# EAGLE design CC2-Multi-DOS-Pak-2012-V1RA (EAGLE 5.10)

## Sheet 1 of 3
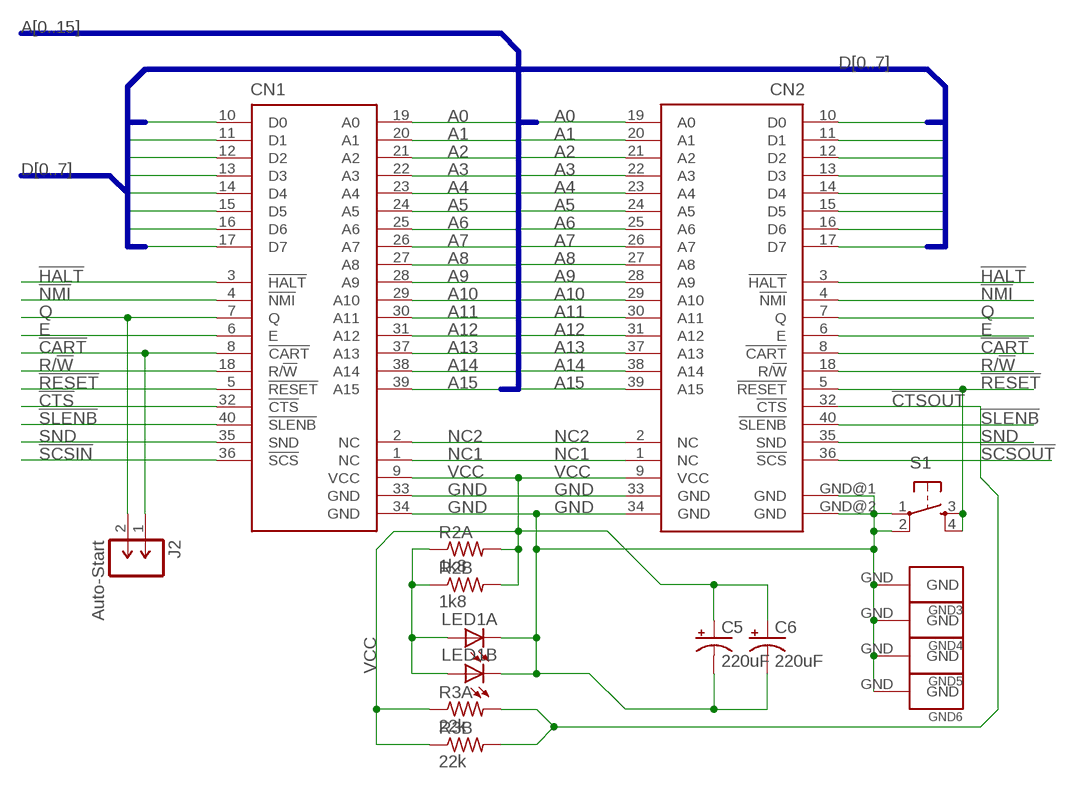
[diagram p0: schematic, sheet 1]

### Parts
C5  220uF  P-CAPACITOR-CPOL-RADIAL-1  [CPOL-RADIAL-1]
C6  220uF  P-CAPACITOR-CPOL-RADIAL-1  [CPOL-RADIAL-1]
CN1  COCO3-CARTRIDGE-PLUG-MEDIUM  [EDGE-CARD-PLUG-2X20-100-MEDIUM]
CN2  COCO3-CARTRIDGE-SLOT-HEADER/SLOT-40  [HEADER/EDGE-CARD-RECEPTACLE-2X20-100-STRAIGHT-W/EARS]
GND3  GROUNDING-STAND-OFF  [STAND-OFF]
GND4  GROUNDING-STAND-OFF  [STAND-OFF]
GND5  GROUNDING-STAND-OFF  [STAND-OFF]
GND6  GROUNDING-STAND-OFF  [STAND-OFF]
J2  Auto-Start  1X02-SIP-100-32  [SIL1X02-100]
LED1A  LED5MM  [LED5MM]
LED1B  LEDCHIPLED_1206  [CHIPLED_1206]
R2A  1k8  RESISTOR  [0207/10]
R2B  1k8  RESISTOR-M1206  [M1206]
R3A  22k  RESISTOR  [0207/10]
R3B  22k  RESISTOR-M1206  [M1206]
S1  RESET  TAC_SWITCHPTH  [TACTILE-PTH]

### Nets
!CART: CN1.8(!CART) CN2.8(!CART) J2.1
!CTS: CN1.32(!CTS) ; also sheet 3
!CTSOUT: CN2.32(!CTS) R3A.2 R3B.2
!HALT: CN1.3(!HALT) CN2.3(!HALT)
!NMI: CN1.4(!NMI) CN2.4(!NMI)
!RESET: CN1.5(!RESET) CN2.5(!RESET) S1.3 S1.4 ; also sheet 3
!SCSIN: CN1.36(!SCS) ; also sheet 2
!SCSOUT: CN2.36(!SCS) ; also sheet 2
!SLENB: CN1.40(!SLENB) CN2.40(!SLENB)
A0: CN1.19(A0) CN2.19(A0) ; also sheet 2,3
A1: CN1.20(A1) CN2.20(A1) ; also sheet 2,3
A2: CN1.21(A2) CN2.21(A2) ; also sheet 2,3
A3: CN1.22(A3) CN2.22(A3) ; also sheet 2,3
A4: CN1.23(A4) CN2.23(A4) ; also sheet 2,3
A5: CN1.24(A5) CN2.24(A5) ; also sheet 2,3
A6: CN1.25(A6) CN2.25(A6) ; also sheet 2,3
A7: CN1.26(A7) CN2.26(A7) ; also sheet 2,3
A8: CN1.27(A8) CN2.27(A8) ; also sheet 3
A9: CN1.28(A9) CN2.28(A9) ; also sheet 3
A10: CN1.29(A10) CN2.29(A10) ; also sheet 3
A11: CN1.30(A11) CN2.30(A11) ; also sheet 3
A12: CN1.31(A12) CN2.31(A12) ; also sheet 3
A13: CN1.37(A13) CN2.37(A13) ; also sheet 3
A14: CN1.38(A14) CN2.38(A14) ; also sheet 3
A15: CN1.39(A15) CN2.39(A15)
D0: CN1.10(D0) CN2.10(D0) ; also sheet 3
D1: CN1.11(D1) CN2.11(D1) ; also sheet 3
D2: CN1.12(D2) CN2.12(D2) ; also sheet 3
D3: CN1.13(D3) CN2.13(D3) ; also sheet 3
D4: CN1.14(D4) CN2.14(D4) ; also sheet 3
D5: CN1.15(D5) CN2.15(D5) ; also sheet 3
D6: CN1.16(D6) CN2.16(D6) ; also sheet 3
D7: CN1.17(D7) CN2.17(D7) ; also sheet 3
E: CN1.6(E) CN2.6(E) ; also sheet 2
GND [power]: C5.2(-) C6.2(-) CN1.33(GND) CN1.34(GND) CN2.33(GND) CN2.34(GND) CN2.GND@1(GND) CN2.GND@2(GND) GND3.GND GND4.GND GND5.GND GND6.GND LED1A.K(C) LED1B.C S1.1 S1.2 ; also sheet 2,3
N$2: LED1A.A LED1B.A R2A.1 R2B.1
NC1 [power]: CN1.1(NC) CN2.1(NC)
NC2 [power]: CN1.2(NC) CN2.2(NC)
Q: CN1.7(Q) CN2.7(Q) J2.2 ; also sheet 2
R/!W: CN1.18(R/!W) CN2.18(R/!W) ; also sheet 2
SND: CN1.35(SND) CN2.35(SND)
VCC [power]: C5.1(+) C6.1(+) CN1.9(VCC) CN2.9(VCC) R2A.2 R2B.2 R3A.1 R3B.1 ; also sheet 2,3

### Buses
A[0..15]
D[0..7]

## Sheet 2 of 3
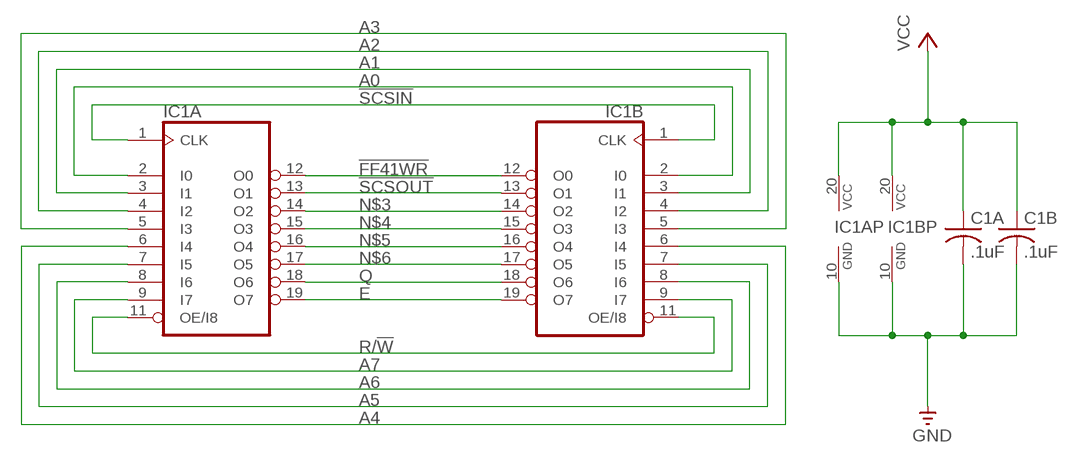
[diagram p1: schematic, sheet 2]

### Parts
C1A  .1uF  NP-CAPACITOR-C050-025X075  [C050-025X075]
C1B  .1uF  NP-CAPACITOR-C1206K  [C1206K]
IC1A  16V8  [DIL20]
IC1B  16V8-S20  [S20]

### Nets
!FF41WR: IC1A.12(O0) IC1B.12(O0) ; also sheet 3
!SCSIN: IC1A.1(CLK) IC1B.1(CLK) ; also sheet 1
!SCSOUT: IC1A.13(O1) IC1B.13(O1) ; also sheet 1
A0: IC1A.2(I0) IC1B.2(I0) ; also sheet 1,3
A1: IC1A.3(I1) IC1B.3(I1) ; also sheet 1,3
A2: IC1A.4(I2) IC1B.4(I2) ; also sheet 1,3
A3: IC1A.5(I3) IC1B.5(I3) ; also sheet 1,3
A4: IC1A.6(I4) IC1B.6(I4) ; also sheet 1,3
A5: IC1A.7(I5) IC1B.7(I5) ; also sheet 1,3
A6: IC1A.8(I6) IC1B.8(I6) ; also sheet 1,3
A7: IC1A.9(I7) IC1B.9(I7) ; also sheet 1,3
E: IC1A.19(O7) IC1B.19(O7) ; also sheet 1
GND [power]: C1A.2(-) C1B.2(-) IC1A.10(GND) IC1B.10(GND) ; also sheet 1,3
N$3: IC1A.14(O2) IC1B.14(O2)
N$4: IC1A.15(O3) IC1B.15(O3)
N$5: IC1A.16(O4) IC1B.16(O4)
N$6: IC1A.17(O5) IC1B.17(O5)
Q: IC1A.18(O6) IC1B.18(O6) ; also sheet 1
R/!W: IC1A.11(OE/I8) IC1B.11(OE/I8) ; also sheet 1
VCC [power]: C1A.1(+) C1B.1(+) IC1A.20(VCC) IC1B.20(VCC) ; also sheet 1,3

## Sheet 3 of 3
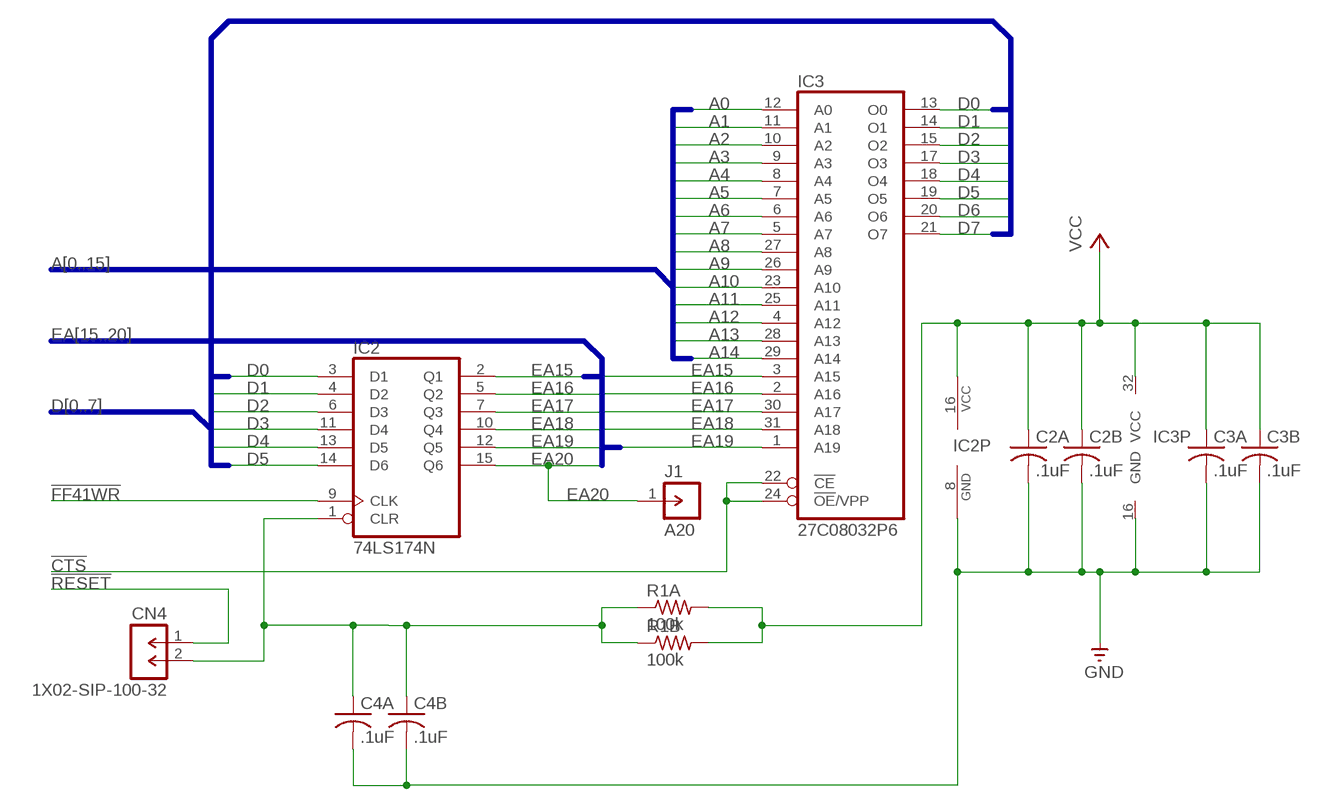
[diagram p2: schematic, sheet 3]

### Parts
C2A  .1uF  NP-CAPACITOR-C050-025X075  [C050-025X075]
C2B  .1uF  NP-CAPACITOR-C1206K  [C1206K]
C3A  .1uF  NP-CAPACITOR-C050-025X075  [C050-025X075]
C3B  .1uF  NP-CAPACITOR-C1206K  [C1206K]
C4A  .1uF  NP-CAPACITOR-C050-025X075  [C050-025X075]
C4B  .1uF  NP-CAPACITOR-C1206K  [C1206K]
CN4  1X02-SIP-100-32  [SIL1X02-100]
IC2  74LS174N  [DIL16]
IC3  27C08032P6  [DIL32-6]
J1  A20  1X01-SIL1X01-100  [SIL1X01-100]
R1A  100k  RESISTOR  [0207/10]
R1B  100k  RESISTOR-M1206  [M1206]

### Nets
!CTS: IC3.22(!CE) IC3.24(!OE!/VPP) ; also sheet 1
!FF41WR: IC2.9(CLK) ; also sheet 2
!RESET: CN4.1 ; also sheet 1
A0: IC3.12(A0) ; also sheet 1,2
A1: IC3.11(A1) ; also sheet 1,2
A2: IC3.10(A2) ; also sheet 1,2
A3: IC3.9(A3) ; also sheet 1,2
A4: IC3.8(A4) ; also sheet 1,2
A5: IC3.7(A5) ; also sheet 1,2
A6: IC3.6(A6) ; also sheet 1,2
A7: IC3.5(A7) ; also sheet 1,2
A8: IC3.27(A8) ; also sheet 1
A9: IC3.26(A9) ; also sheet 1
A10: IC3.23(A10) ; also sheet 1
A11: IC3.25(A11) ; also sheet 1
A12: IC3.4(A12) ; also sheet 1
A13: IC3.28(A13) ; also sheet 1
A14: IC3.29(A14) ; also sheet 1
D0: IC2.3(D1) IC3.13(O0) ; also sheet 1
D1: IC2.4(D2) IC3.14(O1) ; also sheet 1
D2: IC2.6(D3) IC3.15(O2) ; also sheet 1
D3: IC2.11(D4) IC3.17(O3) ; also sheet 1
D4: IC2.13(D5) IC3.18(O4) ; also sheet 1
D5: IC2.14(D6) IC3.19(O5) ; also sheet 1
D6: IC3.20(O6) ; also sheet 1
D7: IC3.21(O7) ; also sheet 1
EA15: IC2.2(Q1) IC3.3(A15)
EA16: IC2.5(Q2) IC3.2(A16)
EA17: IC2.7(Q3) IC3.30(A17)
EA18: IC2.10(Q4) IC3.31(A18)
EA19: IC2.12(Q5) IC3.1(A19)
EA20: IC2.15(Q6) J1.1
GND [power]: C2A.2(-) C2B.2(-) C3A.2(-) C3B.2(-) C4A.2(-) C4B.2(-) IC2.8(GND) IC3.16(GND) ; also sheet 1,2
N$19: C4A.1(+) C4B.1(+) CN4.2 IC2.1(CLR) R1A.1 R1B.1
VCC [power]: C2A.1(+) C2B.1(+) C3A.1(+) C3B.1(+) IC2.16(VCC) IC3.32(VCC) R1A.2 R1B.2 ; also sheet 1,2

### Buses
A[0..15]
D[0..7]
EA[15..20]

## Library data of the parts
C1A C1B C2A C2B C3A C3B C4A C4B = GIMEchip-Capacitor:NP-CAPACITOR: NON-POLARIZED CAPACITOR
C5 C6 = GIMEchip-Capacitor:P-CAPACITOR: POLARIZED CAPACITOR
CN1 = GIMEchip-TRS-80-CoCo-3-Program-Pak-Cartridge:COCO3-CARTRIDGE-PLUG: CoCo 3 Program Pak Cartridge Plug - http://www.GIMEchip.com/ Tandy Radio Shack TRS-80 Color Computer 3 Program Pak Cartridge Plug (Edge-Card) E.A.G.L.E. Library Part created by John Eric Turner & His Father - sales@gimechip.com 40-Pin Edge-Card sharing the same pinout as the Program Pak Cartridge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
CN2 = GIMEchip-TRS-80-CoCo-3-Program-Pak-Cartridge:COCO3-CARTRIDGE-SLOT: CoCo 3 Program Pak Cartridge Slot HEADER/SLOT - http://www.GIMEchip.com/ Tandy Radio Shack TRS-80 Color Computer 3 Program Pak Cartridge Slot HEADER/SLOT E.A.G.L.E. Library Part created by John Eric Turner & His Father - sales@gimechip.com 40-Pin Header and Slot sharing the same pinout as the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
CN4 J2 = GIMEchip-Header-Generic:1X02: MALE HEADER
GND3-GND6 = GIMEchip-Grounding:GROUNDING
IC1A IC1B = GIMEchip-PAL:16V8: PAL
IC2 = GIMEchip-74xx-us:74*174: Hex D type FLIP FLOP, clear
IC3 = GIMEchip-EPROM:27C080: 8-Megabit (1Mx8) OTP EPROM
J1 = GIMEchip-Header-Generic:1X01
LED1A LED1B = GIMEchip-LED:LED: LED
R1A R1B R2A R2B R3A R3B = GIMEchip-Resistor:RESISTOR
S1 = GIMEchip-Switch:TAC_SWITCH: Momentary Switch Button commonly used for reset or general input. Spark Fun Electronics SKU : COM-00097

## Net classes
0 default: width 0.203 mm, clearance 0.203 mm
1 power: width 0.762 mm, clearance 0.203 mm

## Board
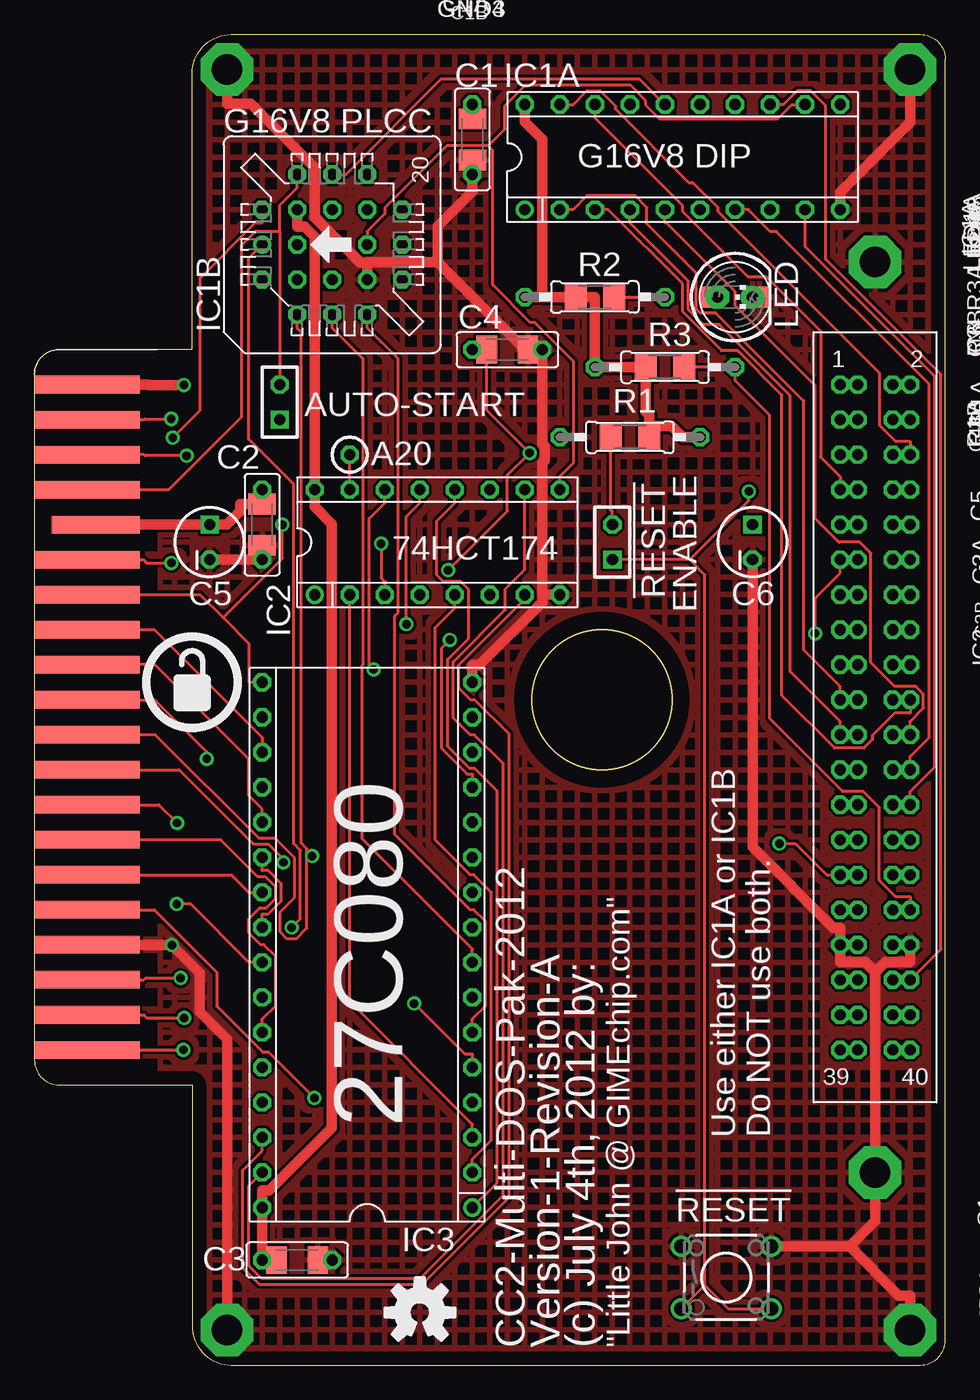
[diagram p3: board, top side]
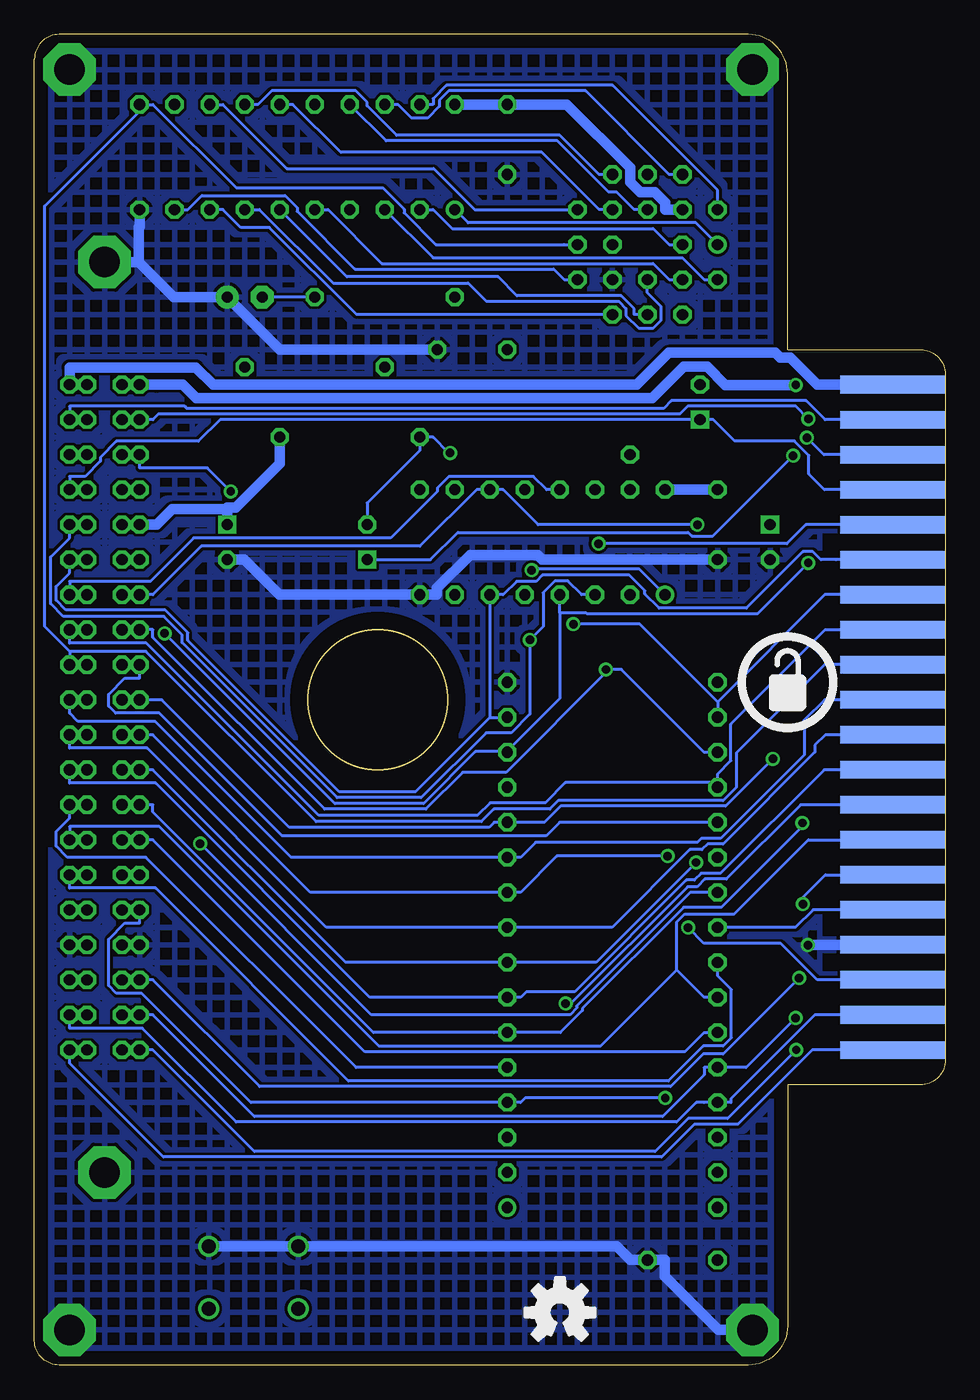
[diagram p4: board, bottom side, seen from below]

Size 66.04 x 96.52 mm. Coordinates in mm from the lower left corner, seen from the top.
Outline: 11.43,73.66 11.43,93.68 arc-90 14.27,96.52 64.24,96.52 arc-90 66.04,94.72 66.04,1.8 arc-90 64.24,0 14.27,0 arc-90 11.43,2.84 11.43,20.32 1.8,20.32 arc-90 0,22.12 0,71.86 arc-90 1.8,73.66 11.43,73.66
Outline: circle at 41.15,48.26 radius 5.08
Copper layers (1*16): Top 0.035mm / dielectric 1.5mm / Bottom 0.035mm
Design rules "default": minimum track width 10mil, minimum drill 24mil, track to track 8mil, track to pad 8mil, pad to pad 8mil, via to via 8mil, smd to smd 8mil, copper to edge 40mil, drill to drill 8mil, minimum pad ring 10mil, minimum via ring 8mil, stop-mask expansion 4mil, vias tented up to drill 0mil, thermal gap 10mil
tRestrict: area 34.8,41.9 to 47.5,54.6
bRestrict: area 34.8,41.9 to 47.5,54.6

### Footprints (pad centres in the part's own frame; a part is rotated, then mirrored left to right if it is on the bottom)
C050-025X075 = drill 0.813 octagon: 1 -2.54,0; 2 2.54,0
C1206K = smd 1.5 x 2: 1 -1.5,0; 2 1.5,0
CPOL-RADIAL-1 = drill 0.813 square: 1 1.27,0 | drill 0.813 octagon: 2 -1.27,0
EDGE-CARD-PLUG-2X20-100-MEDIUM = smd 7.62 x 1.27: 1 3.81,24.13; 3 3.81,21.59; 5 3.81,19.05; 7 3.81,16.51; 11 3.81,11.43; 13 3.81,8.89; 15 3.81,6.35; 17 3.81,3.81; 19 3.81,1.27; 21 3.81,-1.27; 23 3.81,-3.81; 25 3.81,-6.35; 27 3.81,-8.89; 29 3.81,-11.43; 31 3.81,-13.97; 33 3.81,-16.51; 35 3.81,-19.05; 37 3.81,-21.59; 39 3.81,-24.13 | smd 7.62 x 1.27 bottom: 2 3.81,24.13; 4 3.81,21.59; 6 3.81,19.05; 8 3.81,16.51; 10 3.81,13.97; 12 3.81,11.43; 14 3.81,8.89; 16 3.81,6.35; 18 3.81,3.81; 20 3.81,1.27; 22 3.81,-1.27; 24 3.81,-3.81; 26 3.81,-6.35; 28 3.81,-8.89; 30 3.81,-11.43; 32 3.81,-13.97; 34 3.81,-16.51; 36 3.81,-19.05; 38 3.81,-21.59; 40 3.81,-24.13 | smd 6.35 x 1.27: 9 4.445,13.97
HEADER/EDGE-CARD-RECEPTACLE-2X20-100-STRAIGHT-W/EARS = drill 0.813 octagon: 1 -24.13,-2.54; 2 -24.13,2.54; 3 -21.59,-2.54; 4 -21.59,2.54; 5 -19.05,-2.54; 6 -19.05,2.54; 7 -16.51,-2.54; 8 -16.51,2.54; 9 -13.97,-2.54; 10 -13.97,2.54; 11 -11.43,-2.54; 12 -11.43,2.54; 13 -8.89,-2.54; 14 -8.89,2.54; 15 -6.35,-2.54; 16 -6.35,2.54; 17 -3.81,-2.54; 18 -3.81,2.54; 19 -1.27,-2.54; 20 -1.27,2.54; 21 1.27,-2.54; 22 1.27,2.54; 23 3.81,-2.54; 24 3.81,2.54; 25 6.35,-2.54; 26 6.35,2.54; 27 8.89,-2.54; 28 8.89,2.54; 29 11.43,-2.54; 30 11.43,2.54; 31 13.97,-2.54; 32 13.97,2.54; 33 16.51,-2.54; 34 16.51,2.54; 35 19.05,-2.54; 36 19.05,2.54; 37 21.59,-2.54; 38 21.59,2.54; 39 24.13,-2.54; 40 24.13,2.54; 41 -24.13,-1.27; 42 -24.13,1.27; 43 -21.59,-1.27; 44 -21.59,1.27; 45 -19.05,-1.27; 46 -19.05,1.27; 47 -16.51,-1.27; 48 -16.51,1.27; 49 -13.97,-1.27; 50 -13.97,1.27; 51 -11.43,-1.27; 52 -11.43,1.27; 53 -8.89,-1.27; 54 -8.89,1.27; 55 -6.35,-1.27; 56 -6.35,1.27; 57 -3.81,-1.27; 58 -3.81,1.27; 59 -1.27,-1.27; 60 -1.27,1.27; 61 1.27,-1.27; 62 1.27,1.27; 63 3.81,-1.27; 64 3.81,1.27; 65 6.35,-1.27; 66 6.35,1.27; 67 8.89,-1.27; 68 8.89,1.27; 69 11.43,-1.27; 70 11.43,1.27; 71 13.97,-1.27; 72 13.97,1.27; 73 16.51,-1.27; 74 16.51,1.27; 75 19.05,-1.27; 76 19.05,1.27; 77 21.59,-1.27; 78 21.59,1.27; 79 24.13,-1.27; 80 24.13,1.27 | drill 2.2 pad 3.81 octagon: GND@1 -33.02,0; GND@2 33.02,0
SIL1X02-100 = drill 0.813 square: 1 -1.27,0 | drill 0.813 octagon: 2 1.27,0
STAND-OFF = drill 2.2 pad 3.81 octagon: GND 0,0
DIL20 = drill 0.813 round: 1 -11.43,-3.81 | drill 0.813 octagon: 2 -8.89,-3.81; 3 -6.35,-3.81; 4 -3.81,-3.81; 5 -1.27,-3.81; 6 1.27,-3.81; 7 3.81,-3.81; 8 6.35,-3.81; 9 8.89,-3.81; 10 11.43,-3.81; 11 11.43,3.81; 12 8.89,3.81; 13 6.35,3.81; 14 3.81,3.81; 15 1.27,3.81; 16 -1.27,3.81; 17 -3.81,3.81; 18 -6.35,3.81; 19 -8.89,3.81; 20 -11.43,3.81
S20 = drill 0.813 round: 1 0,5.08 | drill 0.813 octagon: 2 0,2.54; 3 -2.54,5.08; 4 -5.08,2.54; 5 -2.54,2.54; 6 -5.08,0; 7 -2.54,0; 8 -5.08,-2.54; 9 -2.54,-5.08; 10 -2.54,-2.54; 11 0,-5.08; 12 0,-2.54; 13 2.54,-5.08; 14 5.08,-2.54; 15 2.54,-2.54; 16 5.08,0; 17 2.54,0; 18 5.08,2.54; 19 2.54,5.08; 20 2.54,2.54
DIL16 = drill 0.813 round: 1 -8.89,-3.81 | drill 0.813 octagon: 2 -6.35,-3.81; 3 -3.81,-3.81; 4 -1.27,-3.81; 5 1.27,-3.81; 6 3.81,-3.81; 7 6.35,-3.81; 8 8.89,-3.81; 9 8.89,3.81; 10 6.35,3.81; 11 3.81,3.81; 12 1.27,3.81; 13 -1.27,3.81; 14 -3.81,3.81; 15 -6.35,3.81; 16 -8.89,3.81
DIL32-6 = drill 0.813 round: 1 -19.05,-7.62 | drill 0.813 octagon: 2 -16.51,-7.62; 3 -13.97,-7.62; 4 -11.43,-7.62; 5 -8.89,-7.62; 6 -6.35,-7.62; 7 -3.81,-7.62; 8 -1.27,-7.62; 9 1.27,-7.62; 10 3.81,-7.62; 11 6.35,-7.62; 12 8.89,-7.62; 13 11.43,-7.62; 14 13.97,-7.62; 15 16.51,-7.62; 16 19.05,-7.62; 17 19.05,7.62; 18 16.51,7.62; 19 13.97,7.62; 20 11.43,7.62; 21 8.89,7.62; 22 6.35,7.62; 23 3.81,7.62; 24 1.27,7.62; 25 -1.27,7.62; 26 -3.81,7.62; 27 -6.35,7.62; 28 -8.89,7.62; 29 -11.43,7.62; 30 -13.97,7.62; 31 -16.51,7.62; 32 -19.05,7.62
SIL1X01-100 = drill 0.813 octagon: 1 0,0
LED5MM = drill 0.813 pad 1.676 octagon: A -1.27,0 | drill 0.813 pad 1.676 round: K 1.27,0
CHIPLED_1206 = smd 1.5 x 1.5: A 0,-1.75; C 0,1.75
0207/10 = drill 0.813 octagon: 1 -5.08,0; 2 5.08,0
M1206 = smd 1.6 x 2: 1 -1.4,0; 2 1.4,0
TACTILE-PTH = drill 1.016 round: 1 -3.251,2.261; 2 3.251,2.261; 3 -3.251,-2.261; 4 3.251,-2.261

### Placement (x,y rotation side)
C1A  31.75,88.9 270 top
C1B  31.75,88.9 270 top
C2A  16.51,60.96 270 top
C2B  16.51,60.96 270 top
C3A  19.05,7.62 0 top
C3B  19.05,7.62 0 top
C4A  34.29,73.66 0 top
C4B  34.29,73.66 0 top
C5  12.7,59.69 90 top
C6  52.07,59.69 90 top
CN1  0,46.99 0 top
CN2  60.96,46.99 270 top
CN4  41.91,59.69 90 top
GND3  13.97,93.98 0 top
GND4  63.5,93.98 0 top
GND5  63.5,2.54 0 top
GND6  13.97,2.54 0 top
IC1A  46.99,87.63 0 top
IC1B  21.59,81.28 90 top
IC2  29.21,59.69 0 top
IC3  24.13,30.48 90 top
J1  22.86,66.04 0 top
J2  17.78,69.85 90 top
LED1A  50.8,77.47 0 top
LED1B  50.8,77.47 270 top
R1A  43.18,67.31 0 top
R1B  43.18,67.31 0 top
R2A  40.64,77.47 180 top
R2B  40.64,77.47 180 top
R3A  45.72,72.39 0 top
R3B  45.72,72.39 0 top
S1  50.16,6.35 0 top
U$1  [OSHWLOGO_0.3]  11.43,49.53 0 top
U$2  [OSHWLOGO_0.3]  11.43,49.53 0 bottom
U$3  [OSHWLOGO_TOL_0.2]  27.94,3.81 0 top
U$4  [OSHWLOGO_TOL_0.2]  27.94,3.81 0 bottom

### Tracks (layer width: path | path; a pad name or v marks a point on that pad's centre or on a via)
!CART
  Bottom 0.203: CN1.8 8.75,63.5 9.89,64.64 9.89,65.99 10.94,67.03 | 10.94,67.03 | 10.94,67.03 15.27,67.03 16.82,68.58 J2.1 52.57,68.58 54.15,67 60.09,67 61.26,65.83 61.26,65.57 62.36,64.47 63.5,64.47 CN2.8
!CTS
  Top 0.203: IC3.22 16.51,35.87 16.94,35.87 17.9,34.9 17.9,33.68 16.94,32.72 16.51,32.72 IC3.24
  Bottom 0.203: CN1.32 9.59,33.02 10.86,31.75 15.55,31.75 IC3.24
!CTSOUT
  Top 0.203: R3B.2 R3A.2 50.8,71.42 53.3,68.92 53.3,46.9 58.6,41.6 60.09,41.6 61.26,40.43 61.26,35.16 62.44,33.98 63.5,33.98 CN2.32
!FF41WR
  Top 0.203: 32.9,88.45 29.91,88.45 25.4,83.95 25.4,83.52 24.13,82.25 IC1B.12 | 32.9,88.45 33.22,88.13 33.22,78.37 35.97,75.62 36.29,75.62 39.1,72.81 39.1,65.47 38.1,64.47 IC2.9 | 32.9,88.45 34.11,89.66 34.11,91.36 35.62,92.87 43.18,92.87 44.31,91.75 44.31,91.43 45.31,90.42 53.9,90.42 54.91,91.44 IC1A.12
!HALT  (via drill 0.61 pad 1.02)
  Top 0.203: v9.92,68.64 7.98,68.64 7.93,68.58 CN1.3
  Bottom 0.203: CN2.3 57.45,68.58 57.05,68.99 19.24,68.99 18.68,69.55 10.83,69.55 v9.92,68.64
!NMI
  Bottom 0.203: CN1.4 8.7,68.58 10.08,69.95 19.85,69.95 20.41,69.39 55,69.39 55.15,69.55 63.5,69.55 CN2.4
!RESET  (via drill 0.61 pad 1.02)
  Top 0.203: 47.5,58.42 51.81,62.73 v51.81,63.38 | v11.03,65.95 8.01,65.95 7.93,66.04 CN1.5 | 48.61,5.79 48.61,57.31 47.5,58.42 | S1.3 48.61,5.79 | S1.4 50.3,4.09 48.61,5.79 | 47.5,58.42 CN4.1
  Bottom 0.203: v51.81,63.38 53.51,65.08 58.42,65.08 CN2.5 | CN4.1 37.32,58.42 35.34,60.4 18.63,60.4 18.38,60.14 16.84,60.14 v11.03,65.95
!SCSIN  (via drill 0.61 pad 1.02)
  Top 0.203: IC1B.1 15.53,80.3 15.53,67.17 18.8,63.9 18.8,37.82 19.28,37.35 19.28,32.37 v18.64,31.74
  Bottom 0.203: v18.64,31.74 17.5,30.6 11.93,30.6 9.27,27.94 7.93,27.94 CN1.36 | IC1B.1 18.09,82.86 34.59,82.86 IC1A.1
!SCSOUT
  Top 0.203: IC1A.13 54.3,91.44 55.32,92.45 56.27,92.45 57.38,91.35 57.38,80.22 65.73,71.87 65.73,30.16 CN2.36
  Bottom 0.203: IC1A.13 52.38,91.44 47.73,86.8 37.1,86.8 34.13,83.82 IC1B.13
!SLENB
  Bottom 0.203: CN2.40 63.5,21.89 56.7,15.09 20.57,15.09 18.19,17.48 15.04,17.48 9.65,22.86 CN1.40
A0  (via drill 0.61 pad 1.02)
  Top 0.203: IC1A.2 39.06,83.82 40.06,84.82 43.56,84.82 44.41,83.97 44.41,82.78 47.99,79.19 47.99,76.59 48.27,76.31 49.41,76.31 55.79,69.93 55.79,51.86 58.42,49.23 CN2.19 | CN1.19 8.72,48.26 12.5,44.48 v12.5,43.97
  Bottom 0.203: IC1B.2 20.02,81.28 21.18,82.45 35.76,82.45 37.13,83.82 IC1A.2 | v12.5,43.97 15.93,40.54 27.89,40.54 29.06,39.37 IC3.12 32.23,39.37 32.71,39.37 33.07,39.01 47.56,39.01 56.8,48.26 57.45,48.26 CN2.19
A1
  Top 0.203: IC1A.3 41.6,83.82 46.99,78.43 46.99,76.42 49.83,73.57 50.99,73.57 54.2,70.37 54.2,48.58 58.02,44.75 60.14,44.75 60.77,45.37 60.77,45.68 62.38,47.3 63.5,47.3 CN2.20
  Bottom 0.203: IC1A.3 37.13,80.31 19.05,80.31 17.48,78.74 IC1B.3 | CN1.20 8.75,48.26 10.23,46.78 10.23,44.25 16.28,38.2 17.69,38.2 17.98,37.91 29.7,37.91 30.79,36.83 IC3.11 47.43,36.83 57.28,46.69 62.89,46.69 63.5,47.3 CN2.20
A2  (via drill 0.61 pad 1.02)
  Top 0.203: CN1.21 8.76,45.72 16.28,38.2 17.46,38.2 18.87,36.8 18.87,33.92 17.81,32.86 17.81,31.42 18.3,30.93 18.98,30.93 19.75,31.7 19.75,36.92 | 19.75,36.92 19.75,37.45 19.34,37.86 19.34,74.95 19.05,75.23 IC1B.4 | 19.75,36.92 v20.13,36.92 | IC1A.4 43.18,82.86 47.42,78.61 47.42,76.56 48.5,75.48 49.66,75.48 54.8,70.34 54.8,50.31 58.42,46.69 CN2.21
  Bottom 0.203: v20.13,36.92 28.16,36.92 30.79,34.29 IC3.10 46.02,34.29 57.45,45.72 CN2.21
A3
  Top 0.203: IC1A.5 45.72,82.86 45.82,82.86 50.8,77.88 50.8,76.86 56.6,71.06 56.6,61.41 58.32,59.69 59.85,59.69 60.65,58.89 60.65,50.95 62.38,49.23 63.91,49.23 64.47,48.67 64.47,47.65 63.5,46.69 CN2.22
  Bottom 0.203: CN1.22 8.7,45.72 9.45,44.97 9.45,44.45 16.11,37.8 17.23,37.8 17.64,37.39 18.51,37.39 24.15,31.75 30.79,31.75 IC3.9 44.88,31.75 57.88,44.76 63.5,44.76 CN2.22 | IC1B.5 20.02,78.74 21.18,79.91 40.84,79.91 44.75,83.82 IC1A.5
A4  (via drill 0.61 pad 1.02)
  Top 0.203: v18.06,36.46 18.06,36.7 16.96,37.8 15.87,37.8 10.49,43.18 CN1.23 | IC1B.6 21.59,75.23 23.85,72.97 23.85,50.86 23.77,50.78 23.77,38.16 31.75,30.18 IC3.8
  Bottom 0.203: v18.06,36.46 25.31,29.21 30.79,29.21 IC3.8 43.48,29.21 57.45,43.18 CN2.23 | v18.06,36.46 | IC1A.6 43.38,78.94 32.43,78.94 31.06,77.57 23.5,77.57 22.55,76.63 22.55,76.2 IC1B.6
A5
  Top 0.203: IC1A.7 51.76,83.82 53.36,82.22 53.8,82.22 64.87,71.15 64.87,45.52 63.5,44.15 CN2.24
  Bottom 0.203: CN1.24 8.78,43.18 16.3,35.66 17.71,35.66 18.19,35.18 18.76,35.18 26.87,27.08 30.38,27.08 30.79,26.67 IC3.7 32.71,26.67 | 32.71,26.67 41.71,26.67 57.26,42.22 63.5,42.22 CN2.24 | 32.71,26.67 | IC1A.7 49.73,83.82 44.39,78.48 34.59,78.48 33.27,77.17 23.66,77.17 23.15,76.65 23.15,76.14 22.22,75.21 21.18,75.21 20.59,75.79 20.59,76.78 21.59,77.78 IC1B.7
A6  (via drill 0.61 pad 1.02)
  Top 0.203: v10.35,39.32 9.03,40.64 CN1.25 | IC1B.8 24.13,75.23 26.37,73 26.37,54.55 26.13,54.32 26.13,38.48 31.59,33.02 31.86,33.02 32.72,32.16 32.72,26.06 31.75,25.09 IC3.6
  Bottom 0.203: v10.35,39.32 10.35,39.09 16.22,33.21 18.96,33.21 26.31,25.86 26.31,25.72 27.91,24.13 IC3.6 32.23,24.13 32.71,24.13 41.47,24.13 57.45,40.11 57.45,40.64 CN2.25 | IC1A.8 52.38,83.82 51.07,82.52 49,82.52 42.68,76.2 IC1B.8
A7  (via drill 0.61 pad 1.02)
  Top 0.203: IC3.5 31.75,22.55 31.21,22.55 v27.53,26.23 | 55.88,82.86 | 55.88,82.86 55.88,81.14 65.28,71.74 65.28,43.38 63.5,41.6 CN2.26 | 55.88,82.86 IC1A.9
  Bottom 0.203: IC3.5 42.72,21.59 57.96,36.83 63.65,36.83 64.48,37.65 64.48,38.7 63.5,39.67 CN2.26 | v27.53,26.23 27.14,26.23 18.67,34.7 17.99,34.7 17.43,35.26 15.86,35.26 10.47,40.64 CN1.26 | IC1B.9 27.64,78.74 28.4,79.5 42.81,79.5 46.99,83.69 46.99,83.96 47.86,84.83 53.9,84.83 54.91,83.82 IC1A.9
A8
  Top 0.203: IC3.27 16.51,25.09 17.48,26.07 17.48,29.63 16.63,30.48 16.41,30.48 15.55,31.35 15.55,32.37 16.34,33.16 16.82,33.16 17.5,33.84 17.5,34.69 16.77,35.42 16.2,35.42 13.52,38.1 CN1.27
  Bottom 0.203: CN2.27 57.45,38.1 42.08,22.72 18.88,22.72 17.48,24.13 IC3.27
A9
  Bottom 0.203: 19.47,28.66 19.47,32.13 18.88,32.72 15.31,32.72 9.93,38.1 CN1.28 | 19.47,28.66 17.48,26.67 17.37,26.67 IC3.26 | 19.47,28.66 25,23.13 41.05,23.13 56.98,39.06 63.5,39.06 CN2.28
A10  (via drill 0.61 pad 1.02)
  Top 0.203: CN2.29 57.45,35.56 55.18,37.83 v54.02,37.83 | IC3.23 15.55,34.29 14.28,35.56 CN1.29
  Bottom 0.203: IC3.23 18.47,34.29 26.72,26.04 26.72,25.89 27.2,25.42 41.61,25.42 v54.02,37.83
A11  (via drill 0.61 pad 1.02)
  Top 0.203: IC3.25 15.55,29.21 11.32,33.44 v10.32,33.44
  Bottom 0.203: CN2.30 63.5,34.59 57.26,34.59 43.27,20.61 20.07,20.61 17.54,23.14 16.1,23.14 15.5,23.73 15.5,27.24 16.51,28.25 IC3.25 | v10.32,33.44 10.32,33.93 8.69,35.56 CN1.30
A12  (via drill 0.61 pad 1.02)
  Top 0.203: CN1.31 8.69,33.02 13.21,28.5 13.21,26.04 16.54,22.72 16.96,22.72 v20.3,19.37
  Bottom 0.203: CN2.31 58.42,32.05 59.48,32.05 60.65,30.88 60.65,27.54 60.09,26.98 58.27,26.98 50.34,19.05 IC3.4 31.27,19.05 30.79,19.05 30.46,19.37 v20.3,19.37
A13  (via drill 0.61 pad 1.02)
  Top 0.203: v10.85,25.18 8.15,25.18 7.93,25.4 CN1.37
  Bottom 0.203: CN2.37 57.45,25.4 50.09,18.04 20.49,18.04 17.48,21.05 17.48,21.59 IC3.28 14.44,21.59 v10.85,25.18
A14
  Bottom 0.203: CN1.38 9.46,25.4 15.55,19.31 15.55,19.05 IC3.29 16.58,19.05 17.48,19.05 18.05,19.05 19.47,17.63 51.42,17.63 58.22,24.43 63.5,24.43 CN2.38
A15  (via drill 0.61 pad 1.02)
  Top 0.203: v10.8,22.86 7.93,22.86 CN1.39
  Bottom 0.203: v10.8,22.86 15.78,17.88 18.64,17.88 21.03,15.5 50.09,15.5 57.45,22.86 CN2.39
D0  (via drill 0.61 pad 1.02)
  Top 0.203: v30.12,52.6 29.5,51.98 29.5,44.76 31.38,42.88 31.75,42.88 IC3.13 | v25.13,59.58 25.13,57.11 25.4,56.84 IC2.3
  Bottom 0.203: CN2.10 63.5,59.99 64.88,58.62 64.88,55.23 63.95,54.31 56.66,54.31 55.33,52.97 55.33,52.4 44.09,41.16 37.99,41.16 33.29,45.86 31.47,45.86 30.12,47.22 v30.12,52.6 29.15,53.57 29.15,56.03 28.3,56.88 27.37,56.88 26.37,55.88 IC2.3 | CN1.10 10.11,60.96 11.49,59.58 v25.13,59.58
D1  (via drill 0.61 pad 1.02)
  Top 0.203: v56.6,53.08 56.6,55.64 58.42,57.45 CN2.11 | CN1.11 7.93,58.42 8.16,58.19 v9.93,58.19
  Bottom 0.203: v56.6,53.08 44.26,40.73 37.83,40.73 34.06,44.5 31.75,44.5 | 31.75,44.5 31.75,44.55 27.94,48.36 27.94,54.56 | 31.75,44.5 IC3.14 | 27.94,54.56 26.03,54.56 25.97,54.5 13.62,54.5 v9.93,58.19 | 27.94,54.56 IC2.4
D2
  Bottom 0.203: 33.02,46.99 33.02,46.98 38.42,41.57 43.92,41.57 54.92,52.57 54.92,53.14 56.56,54.78 63.77,54.78 64.47,55.48 64.47,56.49 63.5,57.45 CN2.12 | CN1.12 7.93,58.42 9.01,58.42 9.59,59 10.32,59 14.42,54.9 20.75,54.9 21.78,55.93 21.78,56.17 22.9,57.29 29.21,57.29 29.66,56.85 31.09,56.85 32.05,55.88 IC2.6 33.02,54.91 33.02,46.99 | 33.02,46.99 IC3.15
D3  (via drill 0.61 pad 1.02)
  Top 0.203: 13.67,54.21 17.97,58.51 v17.97,60.96 | 13.67,54.21 15.55,52.34 15.55,49.53 IC3.17 | CN1.13 12,55.88 13.67,54.21
  Bottom 0.203: v17.97,60.96 29.52,60.96 32.05,63.5 IC2.11 33.98,63.5 38.09,59.4 53.94,59.4 57.45,55.88 CN2.13
D4  (via drill 0.61 pad 1.02)
  Top 0.203: v26.97,53.74 26.97,61.56 27.94,62.53 IC2.13
  Bottom 0.203: CN2.14 63.5,56.84 57.64,56.84 54.49,59.99 40.21,59.99 36.83,63.38 36.83,63.63 35.99,64.47 29.87,64.47 28.91,63.5 IC2.13 | 16.51,48.11 22.14,53.74 v26.97,53.74 | 16.51,48.11 8.74,55.88 CN1.14 | 16.51,48.11 IC3.18
D5  (via drill 0.61 pad 1.02)
  Top 0.203: v24.6,50.46 24.27,50.78 24.27,61.41 25.4,62.53 IC2.14 | IC3.19 16.51,45.52 8.69,53.34 CN1.15
  Bottom 0.203: CN2.15 57.45,53.34 57.45,52.78 45,40.33 37.66,40.33 34.99,43 31.84,43 24.6,50.24 v24.6,50.46 23.48,50.46 17.48,44.45 IC3.19
D6
  Bottom 0.203: 16.51,42.25 27.54,42.25 29,40.79 33.01,40.79 33.92,39.88 45.42,39.88 57.92,52.38 63.5,52.38 CN2.16 | 16.51,42.25 16.51,42.88 15.55,43.84 15.55,46.49 8.7,53.34 CN1.16 | IC3.20 16.51,42.25
D7
  Top 0.203: IC3.21 16.51,40.34 15.55,41.3 15.55,43.96 8.7,50.8 CN1.17
  Bottom 0.203: IC3.21 27.96,39.37 28.93,38.39 48.08,38.39 56.99,47.3 60.16,47.3 60.66,47.79 60.66,48.65 59.48,49.84 58.42,49.84 CN2.17
E  (via drill 0.61 pad 1.02)
  Top 0.203: CN2.6 63.5,67 62.44,67 61.26,68.18 61.26,71.97 49.53,83.71 49.53,83.98 47.73,85.78 47.46,85.78 42.1,91.14 42.1,91.36 41.02,92.44 40.06,92.44 39.06,91.44 IC1A.19 | IC1B.19 16.51,82.86 16.03,82.86 12.02,78.84 12.02,69.26 v10.03,67.27
  Bottom 0.203: IC1B.19 16.51,85.22 24.12,92.83 36.18,92.83 37.13,91.87 37.13,91.44 IC1A.19 | v10.03,67.27 8.8,66.04 CN1.6
EA15
  Top 0.203: IC2.2 22.86,54.91 22.86,26.36 31.75,17.48 IC3.3
EA16
  Top 0.203: IC2.5 30.48,54.91 29.07,53.5 29.07,38.09 31.6,35.56 31.87,35.56 33.13,34.3 33.13,16.32 31.75,14.94 IC3.2
EA17
  Top 0.203: IC2.7 35.56,55.56 30.78,50.77 30.78,49.12 31.63,48.26 31.91,48.26 34.41,45.76 34.41,12.15 28.13,5.87 16.3,5.87 15.1,7.07 15.1,14.13 16.51,15.54 IC3.30
EA18
  Top 0.203: IC3.31 15.54,13 15.54,7.21 16.45,6.3 27.98,6.3 34,12.32 34,43.62 31.91,45.72 31.59,45.72 30.37,46.94 30.37,51.01 34.15,54.79 34.15,56.3 35.56,57.71 IC2.10
EA19
  Top 0.203: IC2.12 30.48,62.53 29.18,61.23 29.18,57.3 29.63,56.84 30.89,56.84 31.48,56.26 31.48,52.7 29.96,51.18 29.96,44.87 31.55,43.28 31.92,43.28 33.54,41.66 33.54,13.22 IC3.1
EA20
  Top 0.203: IC2.15 J1.1
GND  (via drill 0.61 pad 1.02)
  Top 0.762: CN1.34 8.2,30.48 8.22,30.46 v9.96,30.46 11.97,28.45 11.97,25.61 13.97,23.61 GND6.GND | C3A.2 C3B.2 | IC1A.10 58.42,85.06 63.5,90.14 GND4.GND | 29.23,80.01 24.17,80.01 24.13,79.97 | 29.23,80.01 35.58,73.66 C4B.2 C4A.2 36.83,66.82 37,66.65 37,65.62 36.83,65.45 36.83,55.94 36.89,55.88 | 29.23,80.01 29.23,82.6 31.75,85.11 C1A.2 C1B.2 | 24.13,79.97 24.13,79.98 23.61,79.98 20.32,83.28 20.32,86.85 15.68,91.49 13.97,91.49 GND3.GND | 24.13,79.97 IC1B.10 | C5.2 13.95,58.42 C2A.2 C2B.2 | IC3.16 31.75,50.77 32.27,50.77 36.85,55.36 36.85,55.88 36.89,55.88 | IC2.8 36.89,55.88 | GND5.GND 63.5,5.03 62.69,5.03 59.11,8.61 | 59.11,8.61 60.96,10.46 60.96,11.48 CN2.GND@2 60.96,28.51 | S1.2 59.11,8.61 | 60.96,28.51 61.69,29.23 63.5,29.23 CN2.34 | 60.96,28.51 60.23,29.23 58.42,29.23 CN2.33 58.42,31.73 57.92,31.73 52.07,37.57 52.07,57.17 C6.2 | LED1A.K LED1B.C
  Bottom 0.762: CN1.34 9.94,30.48 v9.96,30.46 | C6.2 50.82,58.42 48.28,55.88 IC2.8 36.85,55.88 36.85,56.35 34.45,58.75 29.54,58.75 29.21,58.42 17.75,58.42 C2A.2 | S1.2 S1.1 23.82,8.61 22.84,7.62 C3A.2 20.34,7.62 20.34,6.43 16.46,2.54 GND6.GND | C4A.2 48.26,73.66 LED1A.K 55.93,77.47 58.47,80.01 | IC1A.10 58.42,82.58 58.47,82.53 58.47,80.01 | 58.47,80.01 CN2.GND@1
  pour Bottom (hatched): -1.27,0 67.31,0 67.31,97.79 -1.27,97.79
  pour Top (hatched): -1.27,0 67.31,0 67.31,96.52 -1.27,96.52
N$2
  Top 0.203: R2A.1 44.75,77.47 43.14,77.47 R2B.1 | LED1A.A LED1B.A
  Bottom 0.203: R2A.1 LED1A.A
N$3
  Bottom 0.203: IC1A.14 49.83,91.44 48.84,92.43 42.73,92.43 41.91,91.61 41.91,91.34 39.78,89.2 27.94,89.2 25.09,86.36 IC1B.14
N$4
  Bottom 0.203: IC1B.15 25.09,83.82 29.24,87.97 43.82,87.97 47.29,91.44 IC1A.15
N$5
  Top 0.203: IC1B.16 22.55,86.36 29.49,93.3 43.86,93.3 IC1A.16
N$6
  Bottom 0.203: IC1B.17 22.55,83.82 23.82,85.09 24.41,85.09 28.12,88.8 40.54,88.8 IC1A.17
N$19  (via drill 0.61 pad 1.02)
  Top 0.203: C4A.1 C4B.1 32.79,69.27 v35.9,66.17 34.29,64.56 34.29,61.96 v29.99,57.66 | CN4.2 41.91,61.92 41.78,62.05 41.78,66.66 R1B.1
  Bottom 0.203: CN4.2 41.91,62.53 38.1,66.34 R1A.1 37.13,67.31 35.99,66.17 v35.9,66.17 | v29.99,57.66 29.92,57.73 22.17,57.73 IC2.1
NC1  (via drill 0.61 pad 1.02)
  Top 0.762: v10.83,71.09 8.24,71.09 8.2,71.12 CN1.1
  Bottom 0.762: v10.83,71.09 15.93,71.09 17.26,72.41 18.96,72.41 21.24,70.13 54.29,70.13 55.28,71.12 57.17,71.12 CN2.1
NC2
  Bottom 0.762: CN2.2 63.5,72.36 54.33,72.36 53.09,71.12 22.37,71.12 20.05,73.44 12.32,73.44 11.95,73.07 11.24,73.07 9.29,71.12 CN1.2
Q
  Top 0.203: CN2.7 58.42,64.47 57.01,65.88 57.01,74.98 53.06,78.94 51.74,78.94 46.99,83.69 46.99,84.12 40.64,90.47 IC1A.18 | CN1.7 9.73,63.5 15.02,68.8 15.02,81.22 16.06,82.26 17.78,82.26 | 17.78,82.26 17.78,84.12 19.05,85.39 IC1B.18 | 17.78,82.26 J2.2
  Bottom 0.203: IC1A.18 39.67,91.44 38.69,90.45 37.53,90.45 36.69,91.3 36.69,91.75 36.01,92.42 26.08,92.42 20.02,86.36 IC1B.18
R/!W
  Bottom 0.203: IC1B.11 27.64,81.28 36.93,81.28 39.23,83.58 39.23,83.83 40.78,85.39 51.4,85.39 57.45,91.44 57.94,91.44 | 57.94,91.44 65.31,84.07 65.31,53.58 63.5,51.77 | 57.94,91.44 IC1A.11 | 63.5,51.77 CN2.18 | 63.5,51.77 57.96,51.77 45.62,39.42 33.64,39.42 32.72,40.34 28.67,40.34 28.06,40.95 16.1,40.95 15.14,41.9 15.14,44.4 8.74,50.8 CN1.18
SND  (via drill 0.61 pad 1.02)
  Top 0.203: v10.6,28.07 8.05,28.07 7.93,27.94 CN1.35
  Bottom 0.203: CN2.35 57.45,27.94 49.71,20.2 19.91,20.2 17.55,22.55 16.11,22.55 v10.6,28.07
VCC
  Top 0.762: C1A.1 C1B.1 | C2A.1 C2B.1 14.93,62.46 14.93,61.94 13.95,60.96 C5.1 CN1.9 | IC1B.20 19.05,82.58 19.58,82.58 20.32,81.84 20.32,64.75 IC2.16 20.32,62.26 21.57,61.01 21.57,17.22 17.03,12.68 16.51,12.68 IC3.32 C3A.1 C3B.1 | 36.83,77.47 R2B.2 40.62,77.47 40.64,77.45 R3A.1 42.94,72.39 R3B.1 44.32,69.15 44.58,68.89 44.58,68.1 | 36.83,77.47 R2A.2 | 36.83,77.47 36.83,88.92 35.56,90.19 IC1A.20 | R1A.2 47.01,67.31 46.22,68.1 44.58,68.1 | 44.58,68.1 R1B.2
  Bottom 0.762: IC1A.20 C1A.1 27.43,91.44 22.84,86.84 22.84,85.81 22.12,85.09 21.05,85.09 20.3,84.34 20.3,83.82 IC1B.20 | R1A.2 48.26,65.38 51.44,62.2 52.07,62.2 52.07,62.08 | CN2.9 57.17,60.96 56.05,62.08 52.07,62.08 | 52.07,62.08 C6.1 | IC2.16 19.07,63.5 C2A.1

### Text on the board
tPlace: C1 | IC1A | G16V8 PLCC | G16V8 DIP | R2 | IC1B | C4 | LED | R3 | AUTO-START | R1 | C2 | A20 | 74HCT174 | !RESET | C5 | ENABLE | C6 | IC2 | 27C080 | Use either IC1A or IC1B | Do NOT use both. | !RESET | C3 | CC2-Multi-DOS-Pak-2012 | Version-1-Revision-A | (c) July 4th, 2012 by: | "Little John @ GIMEchip.com"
